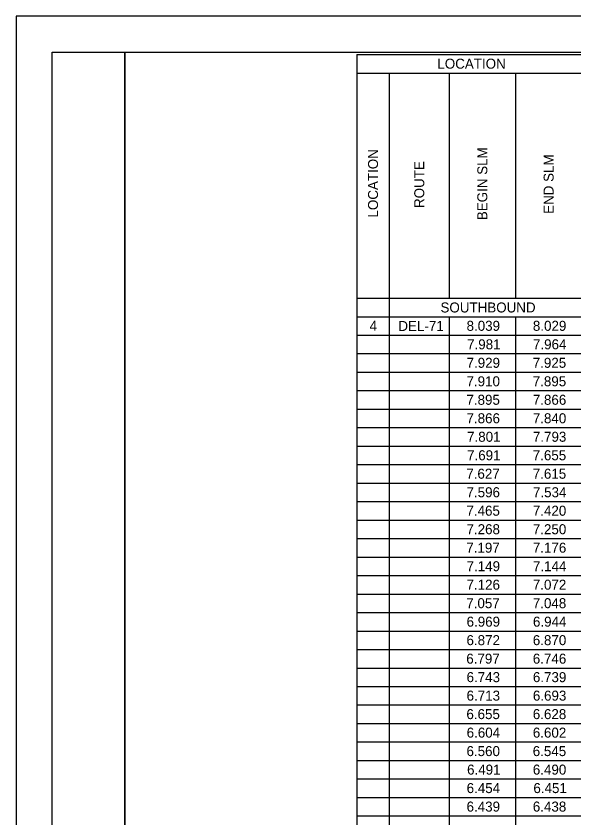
# Model space of a CAD drawing. Extents: x 0 to 34, y 0 to 22.
# Drawn here: x 0 to 7.7, y 10.94 to 22 of the extents above; entities that cross this region are included whole.
import ezdxf

# ---------------------------------------------------------------- set-up
doc = ezdxf.new("R2010")
doc.units = 0
for name, color, linetype in [('Default', 7, 'Continuous'), ('SH_Border', 7, 'Continuous'), ('SH_Cut_Line', 7, 'Continuous')]:
    doc.layers.add(name, color=color, linetype=linetype)

msp = doc.modelspace()

# ---------------------------------------------------------------- linework, layer by layer
at = {"layer": 'Default'}
for p, q in [((4.701, 21.469), (28.761, 21.469)), ((4.701, 21.469), (4.701, 0.844)), ((4.701, 21.214), (28.761, 21.214)), ((5.151, 21.214), (5.151, 1.249)), ((5.976, 21.214), (5.976, 18.109)), ((6.891, 21.214), (6.891, 18.109)), ((4.701, 18.109), (28.761, 18.109)), ((4.701, 17.854), (28.761, 17.854)), ((5.976, 17.854), (5.976, 1.249)), ((6.891, 17.854), (6.891, 1.249)), ((4.701, 17.599), (28.761, 17.599)), ((4.701, 17.344), (28.761, 17.344)), ((4.701, 17.089), (28.761, 17.089)), ((4.701, 16.834), (28.761, 16.834)), ((4.701, 16.579), (28.761, 16.579)), ((4.701, 16.324), (28.761, 16.324)), ((4.701, 16.069), (28.761, 16.069)), ((4.701, 15.814), (28.761, 15.814)), ((4.701, 15.559), (28.761, 15.559)), ((4.701, 15.304), (28.761, 15.304)), ((4.701, 15.049), (28.761, 15.049)), ((4.701, 14.794), (28.761, 14.794)), ((4.701, 14.539), (28.761, 14.539)), ((4.701, 14.284), (28.761, 14.284)), ((4.701, 14.029), (28.761, 14.029)), ((4.701, 13.774), (28.761, 13.774)), ((4.701, 13.519), (28.761, 13.519)), ((4.701, 13.264), (28.761, 13.264)), ((4.701, 13.009), (28.761, 13.009)), ((4.701, 12.754), (28.761, 12.754)), ((4.701, 12.499), (28.761, 12.499)), ((4.701, 12.244), (28.761, 12.244)), ((4.701, 11.989), (28.761, 11.989)), ((4.701, 11.734), (28.761, 11.734)), ((4.701, 11.479), (28.761, 11.479)), ((4.701, 11.224), (28.761, 11.224)), ((4.701, 10.969), (28.761, 10.969))]:
    msp.add_line(p, q, dxfattribs=at)
at = {"layer": 'SH_Border'}
for points in [[(0.5, 21.5), (1.5, 21.5), (1.5, 0.5), (0.5, 0.5)], [(1.5, 21.5), (33.5, 21.5), (33.5, 0.5), (1.5, 0.5)]]:
    msp.add_lwpolyline(points, close=True, dxfattribs=at)
at = {"layer": 'SH_Cut_Line'}
msp.add_lwpolyline([(0, 0), (34, 0), (34, 22), (0, 22)], close=True, dxfattribs=at)

# ---------------------------------------------------------------- texts
at = {"layer": 'Default'}
for s, p in [('LOCATION', (5.814, 21.274)), ('SOUTHBOUND', (5.857, 17.912)), ('4', (4.879, 17.659)), ('DEL-71', (5.276, 17.657)), ('8.039', (6.217, 17.659)), ('8.029', (7.132, 17.659)), ('7.981', (6.224, 17.404)), ('7.964', (7.133, 17.404)), ('7.929', (6.217, 17.149)), ('7.925', (7.13, 17.149)), ('7.910', (6.216, 16.894)), ('7.895', (7.13, 16.894)), ('7.895', (6.215, 16.639)), ('7.866', (7.131, 16.639)), ('7.866', (6.216, 16.384)), ('7.840', (7.131, 16.384)), ('7.801', (6.224, 16.129)), ('7.793', (7.132, 16.129)), ('7.691', (6.224, 15.874)), ('7.655', (7.13, 15.874)), ('7.627', (6.213, 15.619)), ('7.615', (7.13, 15.619)), ('7.596', (6.216, 15.364)), ('7.534', (7.133, 15.364)), ('7.465', (6.215, 15.109)), ('7.420', (7.131, 15.109)), ('7.268', (6.216, 14.854)), ('7.250', (7.131, 14.854)), ('7.197', (6.213, 14.599)), ('7.176', (7.131, 14.599)), ('7.149', (6.217, 14.344)), ('7.144', (7.133, 14.344)), ('7.126', (6.216, 14.089)), ('7.072', (7.131, 14.089)), ('7.057', (6.213, 13.834)), ('7.048', (7.131, 13.834)), ('6.969', (6.217, 13.579)), ('6.944', (7.133, 13.579)), ('6.872', (6.216, 13.324)), ('6.870', (7.131, 13.324)), ('6.797', (6.213, 13.069)), ('6.746', (7.131, 13.069)), ('6.743', (6.217, 12.814)), ('6.739', (7.132, 12.814)), ('6.713', (6.217, 12.559)), ('6.693', (7.132, 12.559)), ('6.655', (6.215, 12.304)), ('6.628', (7.131, 12.304)), ('6.604', (6.218, 12.049)), ('6.602', (7.131, 12.049)), ('6.560', (6.216, 11.794)), ('6.545', (7.13, 11.794)), ('6.491', (6.224, 11.539)), ('6.490', (7.131, 11.539)), ('6.454', (6.218, 11.284)), ('6.451', (7.139, 11.284)), ('6.439', (6.217, 11.029)), ('6.438', (7.131, 11.029))]:
    msp.add_text(s, height=0.138, dxfattribs=at).set_placement(p)
for s, p in [('LOCATION', (4.995, 19.221)), ('BEGIN SLM', (6.503, 19.185)), ('END SLM', (7.418, 19.272)), ('ROUTE', (5.633, 19.353))]:
    msp.add_text(s, height=0.138, rotation=90, dxfattribs=at).set_placement(p)

doc.saveas('drawing.dxf')
